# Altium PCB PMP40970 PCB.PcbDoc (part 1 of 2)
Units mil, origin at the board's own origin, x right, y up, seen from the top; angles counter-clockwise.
Board outline 1445 x 1417.32 mil, 2 copper layers (Top Layer, Bottom Layer), stack 64.8 mil thick; 72 components, 33 nets, 177 pads, 86 vias.
Unrouted connection lines stored in the file: 44.
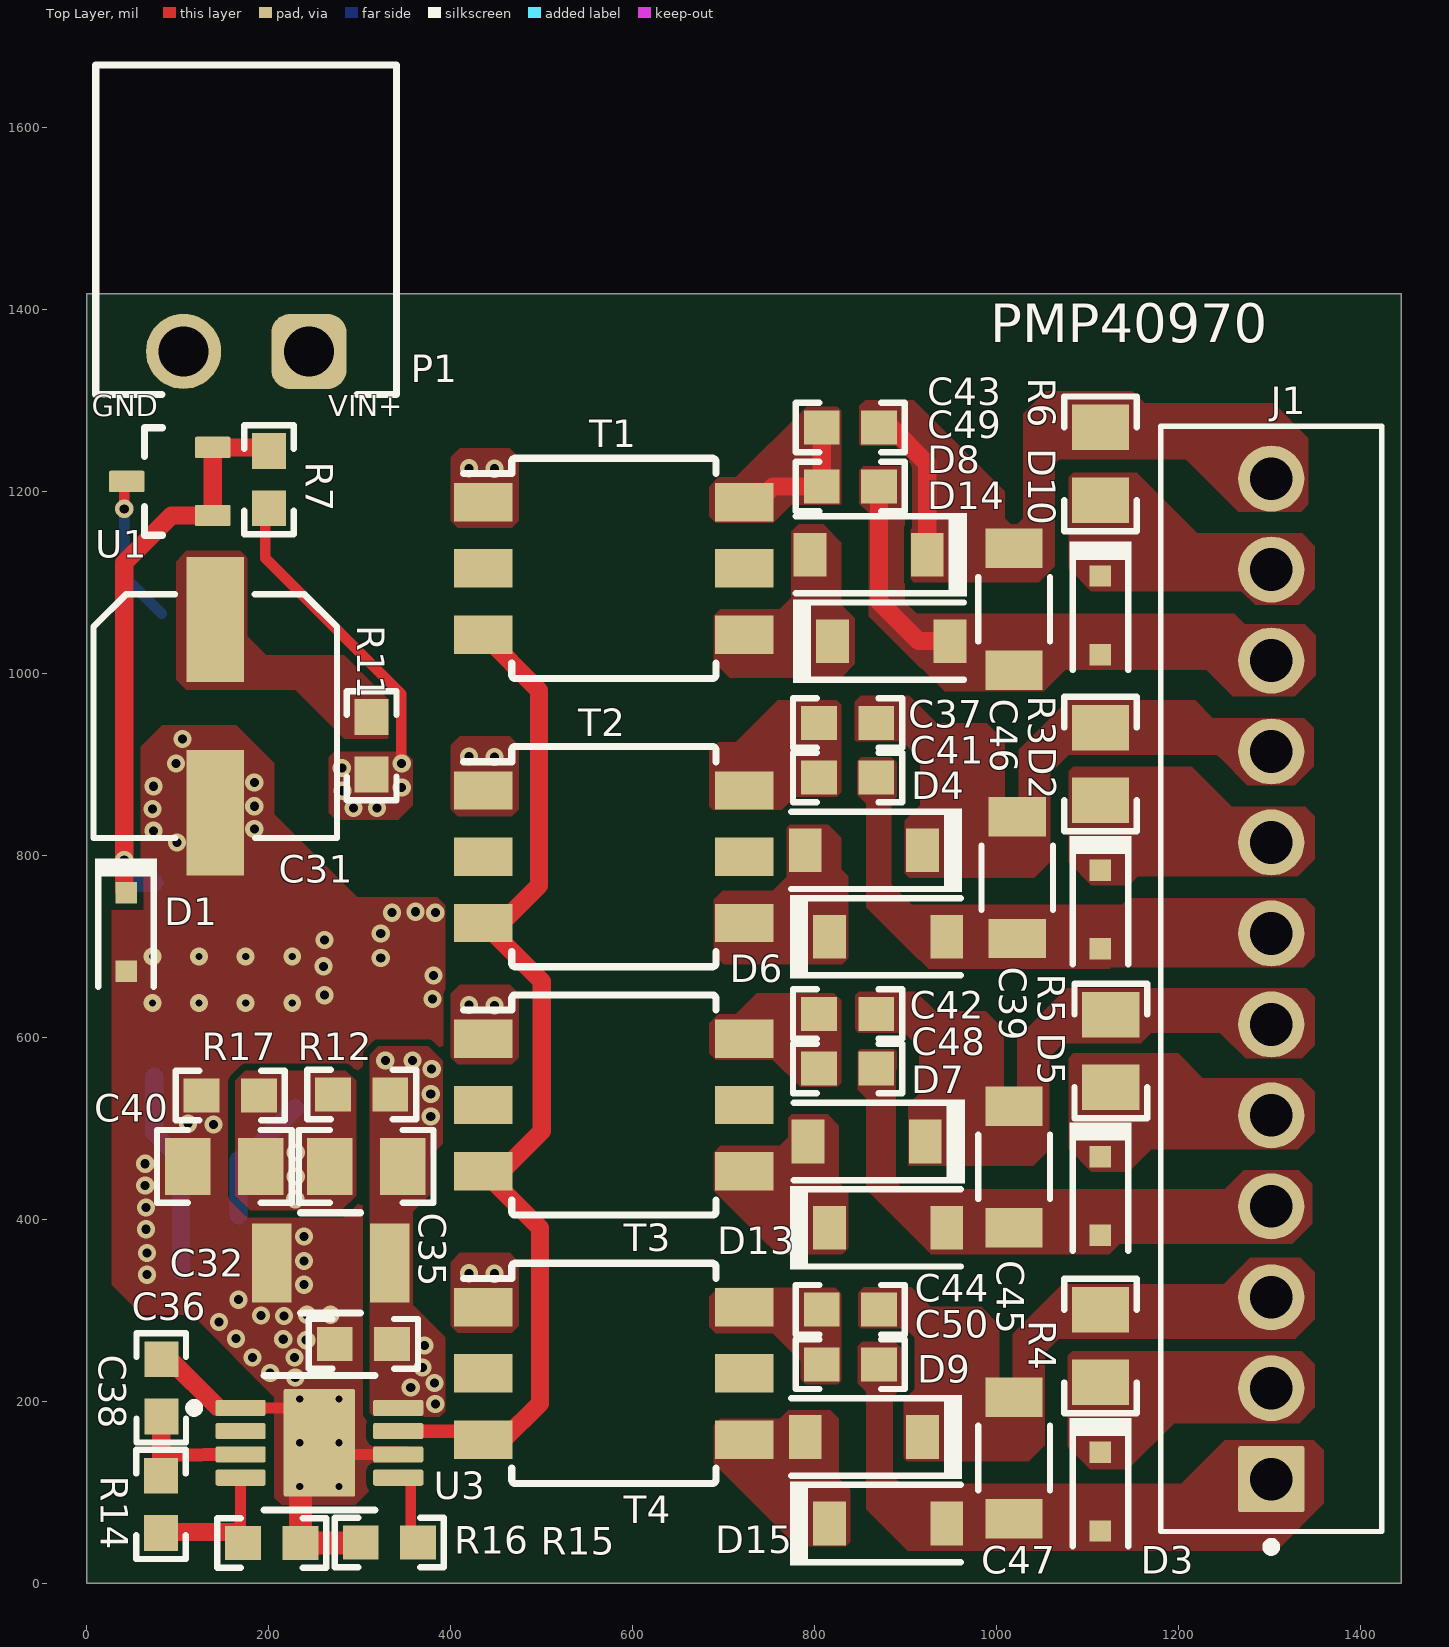
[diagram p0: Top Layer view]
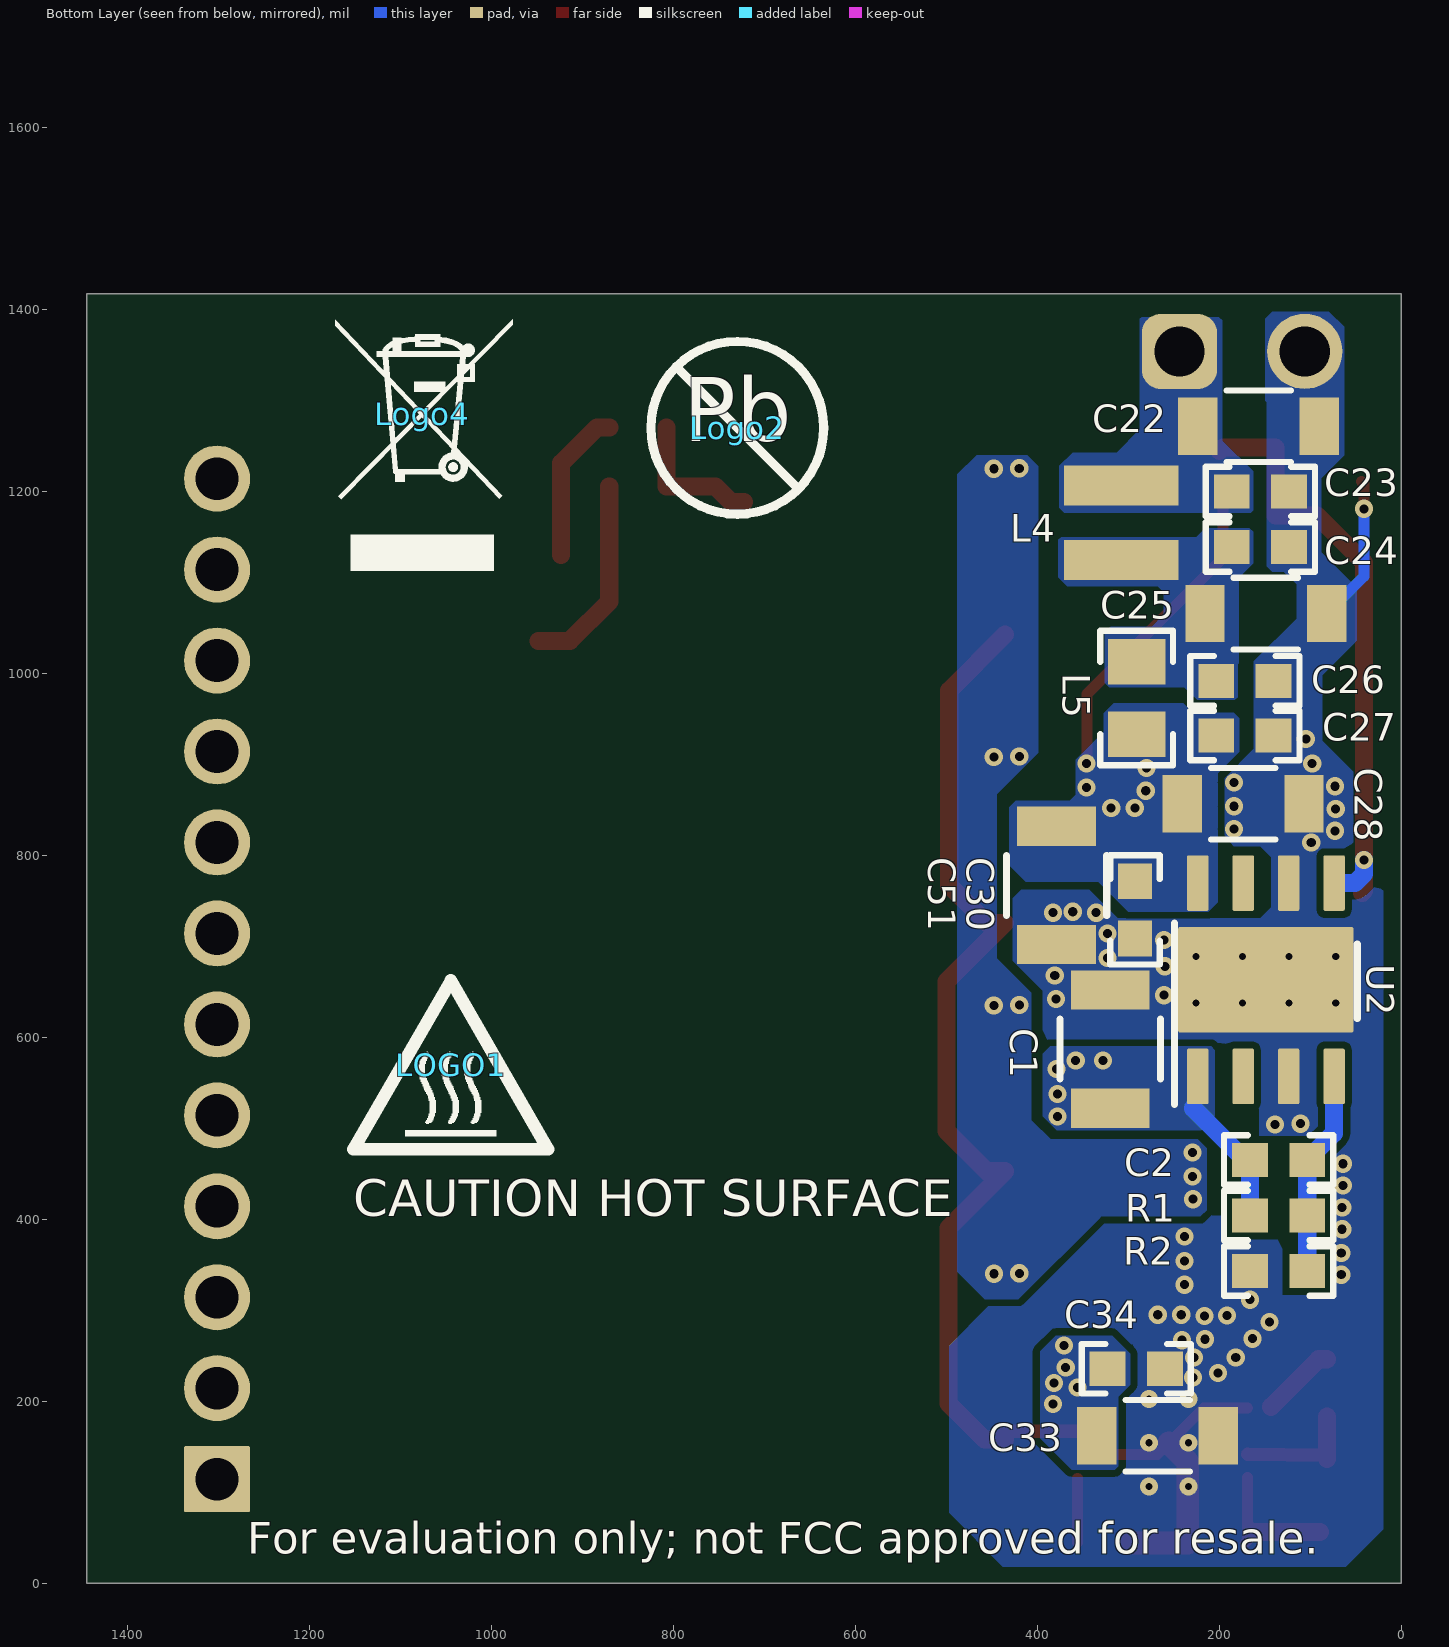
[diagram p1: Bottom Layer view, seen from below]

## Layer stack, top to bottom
Top Solder: solder mask 0.4, Solder Resist, Dk 3.5
Top Layer: signal copper 2.8
Dielectric1: core 59.2, FR-4 High Tg, Dk 4.8
Bottom Layer: signal copper 2.8
Bottom Solder: solder mask 0.4, Solder Resist, Dk 3.5

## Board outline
0,0 1445,0 1445,1417.32 0,1417.32

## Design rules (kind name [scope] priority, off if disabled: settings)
AcuteAngle [All] p1: minimum=4.50000000000000E+0001 checktracksonly=FALSE
AssemblyTestPointUsage [All] p1: valid=2
Clearance Clearance_BoardEdge_MountingHoles [OnCopper and InComponentClass('Mounting Holes') vs IsKeepOut] p1: gap=40 ignorepadtopadclearanceinfootprint=FALSE except(0: Arc-Hole Track-Hole SMDPad-Hole THPad-Hole Via-Hole Fill-Hole Poly-Hole Region-Hole Text-Hole)
Clearance Clearance_BoardEdge_Poly [OnCopper and InPoly vs IsKeepOut] p2: gap=25 ignorepadtopadclearanceinfootprint=FALSE except(0: Arc-Hole Track-Hole SMDPad-Hole THPad-Hole Via-Hole Fill-Hole Poly-Hole Region-Hole Text-Hole)
Clearance Clearance_BoardEdge [OnCopper and Not InComponentClass('Logo') and not InComponentClass('FiducialMark') and not InRegion(1000,500,4000,800) and Not IsKeepout vs IsKeepOut] p3: gap=5 ignorepadtopadclearanceinfootprint=FALSE except(0: Arc-Hole Track-Hole SMDPad-Hole THPad-Hole Via-Hole Fill-Hole Poly-Hole Region-Hole Text-Hole)
Clearance Clearance_Poly [InPolygon] p4: gap=7.8 ignorepadtopadclearanceinfootprint=FALSE
Clearance [All] p5: gap=7.8 ignorepadtopadclearanceinfootprint=FALSE
ComponentClearance ComponentClearance_Logo [All] p1: gap=10 collisioncheckmode=3 verticalgap=10 showdistances=TRUE
ComponentClearance ComponentClearance_ScrewToNut [(HasFootprint('NY PMS 440 0025 PH')) vs (HasFootprint('Keystone_1902C'))] p2: gap=5 collisioncheckmode=3 verticalgap=10 showdistances=FALSE
ComponentClearance ComponentClearance_MountingHoles [InComponentClass('Mounting Holes')] p3: gap=10 collisioncheckmode=3 verticalgap=100000 showdistances=FALSE
ComponentClearance ComponentClearance_SmallPassives [HasFootprint('0201*') or HasFootprint('0402*') or HasFootprint('0508') or HasFootprint('0603*') or HasFootprint('0612') or HasFootprint('0805*') or HasFootprint('0815*') or HasFootprint('0830*') or HasFootprint('1206*') or HasFootprint('1210*') or HasFootprint('1808*') or HasFootprint('1812*') or HasFootprint('1825*') or HasFootprint('2010*') or HasFootprint('2220*') or HasFootprint('2225*') or HasFootprint('2512*') or HasFootprint('2728*') or HasFootprint('3518*') vs HasFootprint('0201*') or HasFootprint('0402*') or HasFootprint('0508') or HasFootprint('0603*') or HasFootprint('0612') or HasFootprint('0805*') or HasFootprint('0815*') or HasFootprint('0830*') or HasFootprint('1206*') or HasFootprint('1210*') or HasFootprint('1808*') or HasFootprint('1812*') or HasFootprint('1825*') or HasFootprint('2010*') or HasFootprint('2220*') or HasFootprint('2225*') or HasFootprint('2512*') or HasFootprint('2728*') or HasFootprint('3518*')] p4: gap=10 collisioncheckmode=3 verticalgap=10 showdistances=FALSE
ComponentClearance ComponentClearance_THtoSMT [IsThruComponent vs IsSMTComponent] p5: gap=10 collisioncheckmode=3 verticalgap=100000 showdistances=FALSE
ComponentClearance ComponentClearance_THtoTH [IsThruComponent vs IsThruComponent] p6: gap=10 collisioncheckmode=3 verticalgap=100000 showdistances=FALSE
ComponentClearance [All] p7: gap=10 collisioncheckmode=3 verticalgap=10 showdistances=FALSE
DiffPairsRouting [All] p1: maxlimit=100 minlimit=10 mostfreqgap=10 toplayer_minwidth=15 toplayer_maxwidth=15 toplayer_prefwidth=15 bottomlayer_minwidth=15 bottomlayer_maxwidth=15 bottomlayer_prefwidth=15 maxuncoupledlength=1000
FabricationTestPointUsage TestPointUsage [All] p1: valid=2 allowmultiple=FALSE
FabricationTestpoint Testpoint [All] p1: side=3 testpointundercomponent=TRUE minsize=40 maxsize=100 preferedsize=60 minholesize=0 maxholesize=40 preferedholesize=32 testpointgrid=1 allowsidetop=TRUE allowsidebottom=TRUE usegrid=TRUE gridtolerance=0.01
FanoutControl Fanout_LCC [IsLCC] p1: bgadir=Out bgaviamode=Centered fanoutstyle=Auto fanoutdirection=Alternating viagrid=1 // Fanout_LCC (Default Rule)
FanoutControl Fanout_BGA [IsBGA] p2: bgadir=Out bgaviamode=Centered fanoutstyle=Auto fanoutdirection=Alternating viagrid=1 // Fanout_BGA (Default Rule)
FanoutControl Fanout_Default [All] p4: bgadir=Out bgaviamode=Centered fanoutstyle=Auto fanoutdirection=Alternating viagrid=1 // Fanout_Default (Default Rule)
FanoutControl Fanout_Small [(CompPinCount < 5)] p5: bgadir=Out bgaviamode=Centered fanoutstyle=Auto fanoutdirection=OutThenIn viagrid=1 // Fanout_Small (Default Rule)
HoleSize [All] p1: absolutevalues=TRUE maxlimit=251 minlimit=6 maxpercent=80.000 minpercent=20.000
MinimumAnnularRing [All] p1: minimumring=3
MinimumSolderMaskSliver MinimumSolderMaskSliver_Logo [InComponentClass('Logo') vs InComponentClass('Logo')] p1: minsoldermaskwidth=0.7
MinimumSolderMaskSliver [All] p2: minsoldermaskwidth=0
PlaneConnect [All] p1: planeconnectstyle=Direct reliefexpansion=10 reliefentries=4 reliefconductorwidth=10 reliefairgap=10
PolygonConnect [All] p1: connectstyle=Direct reliefconductorwidth=10 reliefentries=4 polygonreliefangle="90 Angle" airgapwidth=10
RoutingCorners [All] p1: cornerstyle=45-Degree minsetback=10 maxsetback=100
RoutingVias [All] p1: holewidth=16 width=34 viastyle="Through Hole" minholewidth=8 minwidth=16 maxholewidth=40 maxwidth=65
SMDToCorner [All] p1: distance=0
SilkToBoardRegionClearance [Not ((IsComment or IsDesignator) And (Hide <> 'False')) and not InRegion(1000,500,4000,800)] p1:
SilkToSilkClearance [All] p1: silktosilkclearance=0
SilkToSolderMaskClearance SilkscreenOverComponentPads [IsPad] p1: minsilkscreentomaskgap=0 clearancetoexposedcopper=TRUE
SolderMaskExpansion [All] p1: expansion=3
Width [All] p1: maxlimit=100 minlimit=6 preferedwidth=10 checkconnectedcopper=TRUE
14 further rules are at their usual default settings.

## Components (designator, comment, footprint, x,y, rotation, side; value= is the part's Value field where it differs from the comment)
C1 "UMK325AB7106KMHT" 1210_280 319.98,587 r90 bottom value=10uF
C2 "CGA3E2X7R1H473K080AA" 0603 135,404 r180 bottom value=0.047uF
C22 "GCM31CR71H225KA55L" 1206_180 156.95,1271.65 r180 bottom value=2.2uF
C23 "C0603C222K5RACTU" 0603 154.88,1199.84 r180 bottom value=2200pF
C24 "C0603C222K5RACTU" 0603 154.88,1138.84 r180 bottom value=2200pF
C25 "GCM31CR71H225KA55L" 1206_180 148.88,1065.84 r180 bottom value=2.2uF
C26 "C0603C222K5RACTU" 0603 171.88,991.84 r180 bottom value=2200pF
C27 "C0603C222K5RACTU" 0603 171.88,931.84 r180 bottom value=2200pF
C28 "GCM31CR71H225KA55L" 1206_180 173.88,856.81 r180 bottom value=2.2uF
C30 "06035C104KAZ2A" 0603 293,740 r270 bottom value=0.1uF
C31 "EEHZC1H330XP" SM_RADIAL_6.3BMM 141,953.01 r270 top value=33uF
C32 "UMK325AB7106KMHT" 1210_280 268,352 r180 top value=10uF
C33 "CGA5L3X7R1H475K160AE" 1206_190 268,162 r0 bottom value=4.7uF
C34 "06035C104KAZ2A" 0603 291.45,235.6 r180 bottom value=0.1uF
C35 "CGA4J3X7R1H105K125AB" 0805_HV 307,458 r180 top value=1uF
C36 "06035C104KAZ2A" 0603 304,263.02 r180 top value=0.1uF
C37 "C0603C223K5RACTU" 0603 836.21,945.51 r180 top value=0.022uF
C38 "CGA3E1X7R1E105K080AC" 0603 81.74,214.49 r90 top value=1uF
C39 "CGA5L1X7R1H106K160AC" 1206_190 1022.62,775.51 r270 top value=10uF
C40 "CGA4J3X7R1H105K125AB" 0805_HV 151,458 r180 top value=1uF
C41 "C0603C223K5RACTU" 0603 836.21,885.51 r0 top value=0.022uF
C42 "C0603C223K5RACTU" 0603 836.21,625.51 r180 top value=0.022uF
C43 "C0603C223K5RACTU" 0603 839.24,1270.51 r180 top value=0.022uF
C44 "C0603C223K5RACTU" 0603 839.24,300.51 r180 top value=0.022uF
C45 "CGA5L1X7R1H106K160AC" 1206_190 1019.24,457.44 r270 top value=10uF
C46 "CGA5L1X7R1H106K160AC" 1206_190 1019.24,1070.51 r270 top value=10uF
C47 "CGA5L1X7R1H106K160AC" 1206_190 1019.24,137.44 r270 top value=10uF
C48 "C0603C223K5RACTU" 0603 836.21,565.51 r0 top value=0.022uF
C49 "C0603C223K5RACTU" 0603 839.24,1205.51 r0 top value=0.022uF
C50 "C0603C223K5RACTU" 0603 839.24,240.51 r0 top value=0.022uF
C51 "UMK325AB7106KMHT" 1210_280 379,767 r270 bottom value=10uF
D1 "MMSZ5226BS-7-F" SOD-323 43,715.69 r270 top value=3.3V
D2 "BZT52C5V1S-7-F" SOD-323 1114.24,740.51 r270 top value=5.1V
D3 "BZT52C5V1S-7-F" SOD-323 1114.24,100.51 r270 top value=5.1V
D4 "PMEG6010CEGWJ" SOD-123 854.24,805.51 r180 top value=60V
D5 "BZT52C5V1S-7-F" SOD-323 1114.24,425.51 r270 top value=5.1V
D6 "PMEG6010CEGWJ" SOD-123 880.73,710.51 r0 top value=60V
D7 "PMEG6010CEGWJ" SOD-123 857.18,485.51 r180 top value=60V
D8 "PMEG6010CEGWJ" SOD-123 859.24,1130.51 r180 top value=60V
D9 "PMEG6010CEGWJ" SOD-123 854.24,160.51 r180 top value=60V
D10 "BZT52C5V1S-7-F" SOD-323 1114.24,1063.82 r270 top value=5.1V
D13 "PMEG6010CEGWJ" SOD-123 880.73,390.51 r0 top value=60V
D14 "PMEG6010CEGWJ" SOD-123 884.24,1035.51 r0 top value=60V
D15 "PMEG6010CEGWJ" SOD-123 880.73,65.51 r0 top value=60V
J1 "LHA-12-TS" FP-LHA-12-TS_HDR12-MFG 1302,664.17 r90 top
L4 "XFL3010-102MEB" XFL3010 307.88,1165.84 r270 bottom value=1uH
L5 "782853152" 0805_HV 291,973 r270 bottom value="1500 ohm"
LOGO1 "CAUTION HOT SURFACE" IEC_HotSurface_Small 1045,570 r180 bottom
Logo2 "Pb-Free Symbol" Pb-Free_Overlay_Medium 730,1270 r180 bottom
Logo3 "FCC disclaimer" FCC_disclaimer 1773,621 r90 top
Logo4 "WEEE logo" WEEE_Minimum 1076.5,1285.17 r180 bottom
P1 "691322110002" 691322110002 175.1,1487.86 r180 top
R1 "CRCW060310K0FKEA" 0603 135,465 r0 bottom value=10.0k
R2 "CRCW060310K0FKEA" 0603 135,343 r0 bottom value=10.0k
R3 "CRCW08055K10JNEA" 0805_HV 1114.24,900.51 r90 top value=5.1k
R4 "CRCW08055K10JNEA" 0805_HV 1114.24,260.51 r90 top value=5.1k
R5 "CRCW08055K10JNEA" 0805_HV 1125.67,585 r90 top value=5.1k
R6 "CRCW08055K10JNEA" 0805_HV 1114.24,1230.51 r90 top value=5.1k
R7 "RC0603FR-0720KL" 0603 200,1213.01 r270 top value=20.0k
R11 "CRCW06031R00FKEA" 0603 313,920.5 r270 top value=1.00
R12 "CRCW060310K0FKEA" 0603 302,537 r0 top value=10.0k
R14 "RC0603FR-0716KL" 0603 81.54,86.48 r90 top value=16.0k
R15 "RC0603FR-07100KL" 0603 332.44,44.49 r0 top value=100k
R16 "RC0603FR-0716KL" 0603 203.19,43.99 r180 top value=16.0k
R17 "CRCW060310K0FKEA" 0603 157.5,536 r0 top value=10.0k
T1 "760301107" Wurth_WE-GDT_EP5 579.24,1115.51 r0 top value=650uH
T2 "760301107" Wurth_WE-GDT_EP5 579.23,798.57 r0 top value=650uH
T3 "760301107" Wurth_WE-GDT_EP5 579.22,525.51 r0 top value=650uH
T4 "760301107" Wurth_WE-GDT_EP5 579.21,230.51 r0 top value=650uH
U1 "TL431BQDBZRQ1" DBZ0003A_N 91,1211.04 r180 top
U2 "TPS7B4254QDDARQ1" DDA0008J 148.92,663.25 r90 bottom
U3 "UCC25800DGNRQ1" DGN0008G-MFG 255.58,154.2 r0 top

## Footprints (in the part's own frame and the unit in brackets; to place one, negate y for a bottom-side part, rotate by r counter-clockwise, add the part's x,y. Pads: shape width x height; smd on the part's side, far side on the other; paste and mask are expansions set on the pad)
0603 [mm] "0603 from SM-752 data"
  rect 1x0.95 smd: 1(-0.8,0) 2(0.8,0)
  silkscreen extent -1.52,-0.69 1.52,0.69, body extent -0.87,-0.47 0.87,0.47, height 1
0805_HV [mil] "0805 with 30mil clearance between pads"
  rect 50x63 smd: 1(-40,0) 2(40,0)
  silkscreen extent -74,-40 74,40, body extent -43,-29 43,29, height 57
1206_180 [mm] "1206_180"
  rect 1.1x1.6 smd: 1(-1.7,0) 2(1.7,0)
  silkscreen extent -0.9,-1 0.9,1, body extent -1.75,-0.95 1.75,0.95, height 1.8
1206_190 [mm] "1206_190"
  rect 1.1x1.6 smd: 1(-1.7,0) 2(1.7,0)
  silkscreen extent -0.9,-1 0.9,1, body extent -1.75,-0.95 1.75,0.95, height 1.9
1210_280 [mm] "SMD, 2-Leads, Body 3.6x2.8mm, Height 2.8mm"
  rect 1.1x2.2 smd: 1(-1.65,0) 2(1.65,0)
  silkscreen extent -0.84,-1.4 0.84,1.4, body extent -1.8,-1.4 1.8,1.4, height 2.8
691322110002 [mm] "Horizontal PCB Header, pitch 3.5mm, 02p"
  rrect50% 2.1x2.1 hole 1.4: 1(-1.75,3.4)
  round 2.1 hole 1.4: 2(1.75,3.4)
  silkscreen extent -4.2,-4.6 4.2,4.6, body extent -4.2,-4.6 4.2,4.6, height 7.3
DBZ0003A_N [mm] "SOT23, 3-Leads, Body 2.9x1.3mm, Pitch 0.95mm, Lead Span 2.4mm, IPC Medium Density"
  rrect17% 1x0.6 smd: 1(-1.2,0.95) 2(-1.2,-0.95) 3(1.2,0)
  silkscreen extent 0.2,-1.5 0.7,1.5, body extent -1.26,-1.46 1.26,1.46, height 0.98
DDA0008J [mm] "SOIC, 8-Leads, Body 4.9x3.9mm, Pitch 1.27mm, Exposed Pad"
  rrect14% 1.55x0.6 smd: 1(-2.7,1.905) 2(-2.7,0.635) 3(-2.7,-0.635) 4(-2.7,-1.905) 5(2.7,-1.905) 6(2.7,-0.635) 7(2.7,0.635) 8(2.7,1.905)
  rrect4% 2.95x4.9 smd paste-1.5 mask-1.5: 9(0,0)
  silkscreen extent -3.47,-2.55 1.58,2.55, body extent -3.01,-2.45 3.01,2.45, height 1.57
DGN0008G-MFG [mm]
  rrect22% 1.4x0.45 smd paste+0 mask+0: 1(-2.2,0.975) 2(-2.2,0.325) 3(-2.2,-0.325) 4(-2.2,-0.975) 5(2.2,-0.975) 6(2.2,-0.325) 7(2.2,0.325) 8(2.2,0.975)
  rrect5% 2x3 smd paste-1000 mask-1000: 9(0,0)
  silkscreen extent -3.62,-1.88 1.55,1.88, body extent -3,-1.8 3,1.8, height 0.25
FCC_disclaimer [mil]
FP-LHA-12-TS_HDR12-MFG [mil]
  rrect5% 72.59x72.59 hole 47 paste-39370.1 mask+0: 1(-550,0)
  round 72.59 hole 47 paste-39370.1 mask+0: 2(-450,0) 3(-350,0) 4(-250,0) 5(-150,0) 6(-50,0) 7(50,0) 8(150,0) 9(250,0) 10(350,0) 11(450,0) 12(550,0)
  silkscreen extent -629,-122 608,122, body extent -611,-125 611,125, height 10
IEC_HotSurface_Small [mil]
  silkscreen extent -107,-93 107,92
Pb-Free_Overlay_Medium [mil]
  silkscreen extent -95,-95 95,95
SM_RADIAL_6.3BMM [mm] "Nichicon 6.3x7.7"
  rect 3.5x1.6 smd: 1(-2.7,0) 2(2.7,0)
  silkscreen extent -3.4,-3.4 3.4,3.4, body extent -3.4,-3.4 3.4,3.4, height 8
SOD-123 [mm] "On Semi recommended land pattern"
  rect 0.915x1.22 smd: 1(-1.637,0) 2(1.637,0)
  silkscreen extent -2.74,-1.17 2.03,1.17, body extent -1.93,-0.9 1.93,0.9, height 1.35
SOD-323 [mm] "NXP recommended land pattern"
  rect 0.6x0.6 smd paste-0.05: 1(-1.1,0) 2(1.1,0)
  silkscreen extent -2.06,-0.86 1.53,0.86, body extent -1.3,-0.67 1.3,0.68, height 1.1
WEEE_Minimum [mil] "WEEElie bin"
  silkscreen extent -95,-172 99,104
Wurth_WE-GDT_EP5 [mm] "Gate Drive Transformer, EP5"
  rect 1.63x1.07 smd: 1(-3.645,1.85) 2(-3.645,0) 3(-3.645,-1.85) 4(3.645,-1.85) 5(3.645,0) 6(3.645,1.85)
  silkscreen extent -4.2,-3.08 2.85,3.08, body extent -3.85,-3.08 3.85,3.07, height 5.12
XFL3010 [mm] "Coilcraft"
  rect 1.12x3.2 smd: 1(-1.04,0) 2(1.04,0)
  body extent -1.6,-1.6 1.6,1.6, height 1.1

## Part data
C1 C32 C51: library part CMP-0009258-2, "CAP, CERM, 10 uF, 50 V, +/- 10%, X7R, AEC-Q200 Grade 1, 1210", Cap_Case=1210, MANUFACTURER="Taiyo Yuden", Supplier Part Number 1=587-4326-1-ND, TempCo=X7R, Tolerance_%=10%, Value1=Unknown, Value2=50V, ValueDisplayed=10uF
C2: library part CMP-0007079-2, "CAP, CERM, 0.047 uF, 50 V, +/- 10%, X7R, AEC-Q200 Grade 1, 0603", Cap_Case=0603, MANUFACTURER=TDK, Supplier Part Number 1=445-5664-1-ND, TempCo=X7R, Tolerance_%=10%, Value1="0.049007 ohm", Value2=50V, ValueDisplayed=0.047uF
C22 C25 C28: library part CMP-0008814-2, "CAP, CERM, 2.2 uF, 50 V, +/- 10%, X7R, AEC-Q200 Grade 1, 1206", Cap_Case=1206, MANUFACTURER=MuRata, Supplier Part Number 1=490-4796-1-ND, TempCo=X7R, Tolerance_%=10%, Value1=Unknown, Value2=50V, ValueDisplayed=2.2uF
C23 C24 C26 C27: library part CMP-0006898-4, "CAP, CERM, 2200 pF, 50 V, +/- 10%, X7R, 0603", Cap_Case=0603, MANUFACTURER=Kemet, Supplier Part Number 1=399-1085-1-ND, TempCo=X7R, Tolerance_%=10%, Value1=Unknown, Value2=50V, ValueDisplayed=2200pF
C30 C34 C36: library part CMP-0079095-1, "CAP, CERM, 0.1 µF, 50 V,+/- 10%, X7R, AEC-Q200 Grade 1, 0603", Cap_Case=0603, MANUFACTURER=AVX, Supplier Part Number 1=478-3540-1-ND, TempCo=X7R, Tolerance_%=10%, Value2=50V, ValueDisplayed=0.1µF
C31: library part CMP-0012598-3, "CAP, Polymer Hybrid, 33 uF, 50 V, +/- 20%, 40 ohm, 6.3x7.7 SMD", MANUFACTURER=Panasonic, Supplier Part Number 1=P15464CT-ND, Tolerance_%=20%, Value1="40 ohm", Value2=50V, ValueDisplayed=33uF
C33: library part CMP-0085349-1, "CAP, CERM, 4.7 µF, 50 V,+/- 10%, X7R, AEC-Q200 Grade 1, 1206", Cap_Case=1206, MANUFACTURER=TDK, TempCo=X7R, Tolerance_%=10%, Value2=50V, ValueDisplayed=4.7µF
C35 C40: library part CMP-0007976-2, "CAP, CERM, 1 uF, 50 V, +/- 10%, X7R, AEC-Q200 Grade 1, 0805", Cap_Case=0805, MANUFACTURER=TDK, Supplier Part Number 1=445-6961-1-ND, TempCo=X7R, Tolerance_%=10%, Value1="0.008782 ohm", Value2=50V, ValueDisplayed=1uF
C37 C41 C42 C43 C44 C48 C49 C50: library part CMP-0006901-1, "CAP, CERM, 0.022 uF, 50 V, +/- 10%, X7R, 0603", Cap_Case=0603, MANUFACTURER=Kemet, Supplier Part Number 1=399-1280-1-ND, TempCo=X7R, Tolerance_%=10%, Value1=Unknown, Value2=50V, ValueDisplayed=0.022uF
C38: library part CMP-0076705-3, "CAP, CERM, 1 µF, 25 V,+/- 10%, X7R, AEC-Q200 Grade 1, 0603", Cap_Case=1.6x0.8x0.8mm, MANUFACTURER=TDK, Supplier Part Number 1=445-6931-1-ND, TempCo=X7R, Tolerance_%=10%, Value2=25V, ValueDisplayed=1µF
C39 C45 C46 C47: library part CMP-0085950-1, "CAP, CERM, 10 µF, 50 V,+/- 10%, X7R, AEC-Q200 Grade 1, 1206", Cap_Case=1206, MANUFACTURER=TDK, TempCo=X7R, Tolerance_%=10%, Value2=50V, ValueDisplayed=10µF
D1: library part CMP-0005849-3, "Diode, Zener, 3.3 V, 200 mW, SOD-323", MANUFACTURER="Diodes Inc.", Power_W=200mW, Value1=0.2W
D2 D3 D5 D10: library part CMP-0005865-2, "Diode, Zener, 5.1 V, 200 mW, SOD-323", MANUFACTURER="Diodes Inc.", Power_W=200mW, Value1=0.2W
D4 D6 D7 D8 D9 D13 D14 D15: library part CMP-0079239-1, "Diode, Schottky, 60 V, 1 A, AEC-Q101, SOD-123", MANUFACTURER=Nexperia, Supplier Part Number 1=1727-7340-1-ND, Value1=1A, Value2=0.66V
J1: library part CMP-0089369-1, Current_A=3A, Digikey Part Number=2057-LHA-12-TS-ND, MANUFACTURER="Adam Tech", Operating Temperature Range="-25°C to +85°C", Voltage_V=250V
L4: library part CMP-0061128-1, "Inductor, Shielded, Composite, 1 uH, 2.3 A, 0.04 ohm, SMD", MANUFACTURER=Coilcraft, Value1="0.04 ohm", Value2=2.3A, ValueDisplayed=1uH
L5: library part CMP-0003295-1, "Ferrite Bead, 1500 ohm @ 100 MHz, 0.7 A, 0805", MANUFACTURER="Wurth Elektronik", Supplier Part Number 1=732-6714-1-ND, Value1="0.3 ohm", Value2=0.7A, ValueDisplayed="1500 ohm"
LOGO1: library part CMP-0074837-1, "IEC 61010-1 Hot Surface Warning"
Logo2: library part CMP-0074839-1
Logo3: library part CMP-0074847-1, "FCC_disclaimer"
Logo4: library part CMP-0074769-1
P1: "WR-TBL Serie 3221 Horizontal PCB Header, Pluggable, THT, pitch 3.5mm, 2p", MANUFACTURER="Wurth Elektronik", Operating Temperature="-40 to +105degC", Rated Current [UL]=10A, Working Voltage [UL]=300VAC
R1 R2 R12 R17: library part CMP-0021998-4, "RES, 10.0 k, 1%, 0.1 W, AEC-Q200 Grade 0, 0603", MANUFACTURER=Vishay-Dale, Power_W=100mW, Supplier Part Number 1=541-10.0KHCT-ND, TempCo="100 ppm/C", Tolerance_%=1%, Value2=0.1W, Value_Code=10k0, ValueDisplayed=10.0k
R3 R4 R5 R6: library part CMP-0020572-3, "RES, 5.1 k, 5%, 0.125 W, AEC-Q200 Grade 0, 0805", MANUFACTURER=Vishay-Dale, Power_W=125mW, Supplier Part Number 1=541-5.1KACT-ND, TempCo="200 ppm/C", Tolerance_%=5%, Value2=0.125W, Value_Code=5k10, ValueDisplayed=5.1k
R7: library part CMP-0022906-4, "RES, 20.0 k, 1%, 0.1 W, 0603", MANUFACTURER="Yageo America", Power_W=100mW, Supplier Part Number 1=311-20.0KHRCT-ND, TempCo="100 ppm/C", Tolerance_%=1%, Value2=0.1W, Value_Code=20k0, ValueDisplayed=20.0k
R11: library part CMP-0022170-2, "RES, 1.00, 1%, 0.1 W, 0603", MANUFACTURER=Vishay-Dale, Power_W=100mW, Supplier Part Number 1=52K8059, TempCo="100 ppm/C", Tolerance_%=1%, Value2=0.1W, Value_Code=1R00, ValueDisplayed=1.00
R14 R16: library part CMP-0022831-4, "RES, 16.0 k, 1%, 0.1 W, 0603", MANUFACTURER="Yageo America", Power_W=100mW, Supplier Part Number 1=311-16.0KHRCT-ND, TempCo="100 ppm/C", Tolerance_%=1%, Value2=0.1W, Value_Code=16k0, ValueDisplayed=16.0k
R15: library part CMP-0022735-3, "RES, 100 k, 1%, 0.1 W, 0603", MANUFACTURER="Yageo America", Power_W=100mW, Supplier Part Number 1=311-100KHRCT-ND, TempCo="200 ppm/C", Tolerance_%=1%, Value2=0.1W, Value_Code=100k
T1 T2 T3 T4: library part CMP-0030729-1, "Transformer, Gate Drive, 650 uH, SMT", MANUFACTURER="Wurth Elektronik", Supplier Part Number 1=732-4287-1-ND, ValueDisplayed=650uH
U1: library part CMP-0032986-1, "Automotive Catalog Adjustable Precision Shunt Regulator, 34 ppm / degC, 100 mA, -40 to 125 degC, 3-pin SOT-23 (DBZ), Green (RoHS & no Sb/Br)", MANUFACTURER="Texas Instruments", Rating=Automotive, Temp Coeff(Typ)(ppm/ degree C)=34
U2: library part CMP-0073874-1, "150-mA 40-V Voltage-Tracking LDO With 4-mV Tracking Tolerance, DDA0008J (SOIC-8)", Alternate Manufacturer="Texas Instruments"
U3: library part CMP-0088494-2, "Open Loop LLC Transformer Driver for Isolated Bias Supplies", MANUFACTURER="Texas Instruments", Max Supply Voltage=36V, Min Supply Voltage=12V, Nominal Supply Current=500uA, Operating Temperature Range="-40°C to +150°C", Switching Frequency=100-2000kHz

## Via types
v1: diameter 20, hole 10, Top Layer to Bottom Layer, 72 vias
v2: diameter 19.68, hole 7.87, Top Layer to Bottom Layer, 10 vias
v3: diameter 19.68, hole 7.87, Top Layer to Bottom Layer, tented both sides, 4 vias

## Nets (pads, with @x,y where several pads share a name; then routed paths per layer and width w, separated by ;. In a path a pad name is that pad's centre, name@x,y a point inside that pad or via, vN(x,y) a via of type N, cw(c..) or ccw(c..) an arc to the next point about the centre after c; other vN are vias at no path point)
18V_1: C43.1 C46.1 D8.1 J1.12 R6.2 | length 169.9
  Top Layer w20: C43.1@870.73,1270.51 884.24,1270.51 923.71,1231.04 D8.1@923.71,1130.51
18V_2: C37.1 C39.1 D4.1 J1.9 R3.2
18V_3: C42.1 C45.1 D7.1 J1.6 R5.2
18V_4: C44.1 C47.1 D9.1 J1.3 R4.2
20V: C1.1 C2.1 C32.1 C33.2 C34.1 C35.1 C36.1 R1.2 R12.2 U2.1 U3.8 | length 147.1
  Bottom Layer w20: C2.1@166.5,404 R1.2@166.5,465 171.96,465 229,522.04
  other v1: 383,197 356,215 382,220 369,237 371,261 378,513 378,537.66 379,565 328,574.62 358,574.62
-5V_1: C46.2 C49.2 D10.2 D14.2 J1.10 | length 222.5
  Top Layer w20: C49.2@870.73,1205.51 870.73,1079.01 914.24,1035.51 D14.2@948.71,1035.51
-5V_2: C39.2 C41.2 D2.2 D6.2 J1.7
-5V_3: C45.2 C48.2 D5.2 D13.2 J1.4
-5V_4: C47.2 C50.2 D3.2 D15.2 J1.1
GND: C1.2 C22.2 C23.2 C24.2 C25.2 C26.2 C27.2 C28.2 C30.2 C31.2 C32.2 C33.1 C34.2 C36.2 C38.2 C40.2 C51.2 D1.2 P1.2 R2.2 R15.1 R16.1 R17.1 U1.3 U2.3 U2.6 U2.9 U3.1 U3.6 U3.9 | length 626.2
  Top Layer w12: v1(41,1181) 41,1208.29 U1.3@43.76,1211.04 ; U3.1@168.96,192.59 217.19,192.59 U3.9@255.58,154.2 268.37,141.41 U3.6@342.19,141.41
  Top Layer w20: C38.2@81.74,245.98 91.02,245.98 U3.1@143.27,193.73
  Top Layer w25: U3.9@255.58,154.2 234.68,133.31 R16.1@234.68,43.99 300.44,43.99 R15.1@300.94,44.49
  Bottom Layer w12: v1(41,1181) 41,1106.79 C25.2@81.95,1065.84
  other v1: 229,226 201.43,231 182,248 228,248 241,267 215.8,268 163.77,268.66 145,287 191.49,294 216.5,293.66 242,295 267.75,295 166.5,311.5 238.5,328 66,339 238.5,354 66,362.84 238.5,381 65,389 65,413 64,437 64,461 139,504 111,505 379.8,642 261,646.29 381,668.01 260,678 323,687 261,707 323,714 335.5,737 383,737.01 361.23,738 99,814 73,827 184,829 72.15,851 184,854 73,876 184,880.24 98,901 105,928
  other v2: 233.92,106.17 277.23,106.17 233.92,154.2 277.23,154.2 233.92,202.23 277.23,202.23 123.33,637.66 174.51,637.66 123.33,688.84 174.51,688.84
  other v3: 72.15,637.66 225.69,637.66 72.15,688.84 225.69,688.84
HB: C35.2 C40.1 R12.1 R17.2 T1.1 T2.1 T3.1 T4.1
  other v1: 447.97,340 419.97,340.51 229,422 229.5,447 229.5,473.31 447.98,635 419.98,635.51 447.99,908.06 419.99,908.57 448,1225 420,1225.51
NetC2_2: C2.2 R1.1 R2.1 U2.4 | length 226.2
  Bottom Layer w20: U2.4@73.92,556.95 73.92,494.58 R1.1@103.5,465 R2.1@103.5,343
NetC24_1: C24.1 C25.1 C26.1 L4.2 L5.1
NetC27_1: C27.1 C28.1 C30.1 C51.1 L5.2 R7.2 R11.2 U2.8 | length 343.6
  Top Layer w12: R7.2@196,1182.5 196,1126.9 345.5,977.4 345.5,901.5 v1(346,901)
  other v1: 293,852 319,852 281,871 346,874.5 280.17,896.09
NetC31_1: C31.1 R11.1
NetC37_2: C37.2 C41.1 T2.6
NetC42_2: C42.2 C48.1 T3.6
NetC43_2: C43.2 C49.1 T1.6 | length 157.1
  Top Layer w20: T1.6@722.74,1188.35 737.07,1188.35 754.24,1205.51 C49.1@807.74,1205.51 C43.2@807.74,1270.51
NetC44_2: C44.2 C50.1 T4.6
NetD1_1: D1.1 R7.1 U1.1 U1.2 U2.5 | length 673
  Top Layer w20: D1.1@43,759 41,761 v1(41,795) 41,1121.72 92.92,1173.64 U1.1@138.24,1173.64 U1.2@138.24,1248.44 196.06,1248.44 R7.1@200,1244.51
  Bottom Layer w20: v1(41,795) 41,779.55 51,769.55 U2.5@73.92,769.55
NetD4_2: D4.2 D6.1 T2.4
NetD7_2: D7.2 D13.1 T3.4
NetD8_2: D8.2 D14.1 T1.4
NetD9_2: D9.2 D15.1 T4.4
NetR15_2: R15.2 U3.5 | length 70.7
  Top Layer w12: R15.2@355.93,44.49 U3.5@356,115.16
OC_DT: R14.1 R16.2 U3.4 | length 156.2
  Top Layer w12: R16.2@159.7,55.98 168.96,65.24 ; U3.4@168.96,115.81 168.96,65.24 ; R16.2@171.69,43.99 168.96,46.71 168.96,65.24
  Top Layer w20: R14.1@89.54,55.98 R16.2@159.7,55.98
SGND_1: D10.1 J1.11 R6.1
SGND_2: D2.1 J1.8 R3.1
SGND_3: D5.1 J1.5 R5.1
SGND_4: D3.1 J1.2 R4.1
SW: T1.3 T2.3 T3.3 T4.3 U3.7 | length 1180
  Top Layer w12: T4.3@435.71,157.68 T4.3@435.71,167
  Top Layer w15: U3.7@342.19,167 T4.3@435.71,167
  Top Layer w20: T4.3@435.71,157.68 458.17,157.68 498,197.51 498,390.39 T3.3@435.71,452.68 455.68,452.68 500,497 500,661.46 T2.3@435.73,725.73 455.73,725.73 497,767 497,981.41 T1.3@435.73,1042.68
VIN+: C22.1 C23.1 L4.1 P1.1
VREG: C38.1 R14.2 U3.3 | length 135.7
  Top Layer w12: R14.2@81.74,136.22 85.92,140.41
  Top Layer w15: 85.92,140.41 U3.3@168.96,141.41
  Top Layer w20: R14.2@81.74,136.22 C38.1@81.74,182.99
pads on no net: T1.2 T1.5 T2.2 T2.5 T3.2 T3.5 T4.2 T4.5 U2.2 U2.7 U3.2

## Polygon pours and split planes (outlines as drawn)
18V_1 on Top Layer "TOP_LAYER_18V_1_P276" (solid, remove dead copper, pour order 276): 1139.24,1235.51 1207.88,1235.51 1265.54,1177.84 1334.88,1177.84 1342.88,1185.84 1342.88,1258.84 1304.88,1296.84 1162.9,1296.84 1149.24,1310.51 1054.24,1310.51 1029.24,1285.51 1029.24,1170.51 1022.62,1163.9 1015.85,1163.9 1009.24,1170.51 1009.24,1200.51 909.24,1300.51 855.69,1300.51 849.24,1294.05 849.24,1251.81 850.54,1250.51 889.24,1250.51 904.24,1235.51 904.24,1105.51 909.24,1100.51 1046.64,1100.51 1064.24,1118.11 1064.24,1231.04 1068.71,1235.51
SGND_1 on Top Layer "TOP_LAYER_SGND_1_P274" (solid, remove dead copper, pour order 274): 1164.24,1210.51 1220.83,1153.9 1335.83,1153.9 1349.88,1139.84 1349.88,1093.01 1332.37,1075.51 1284.21,1075.51 1269.21,1090.51 1104.24,1090.51 1079.24,1115.51 1079.24,1215.51 1084.24,1220.51 1154.24,1220.51
-5V_1 on Top Layer "TOP_LAYER_-5V_1_P272" (solid, remove dead copper, pour order 272): 1272.88,1053.84 1261.21,1065.51 912.04,1065.51 899.22,1078.33 899.22,1225.51 896.72,1228.01 889.24,1228.01 850.54,1228.01 849.24,1226.71 849.24,1186.81 859.24,1176.81 859.24,1063.01 916.74,1005.51 917.94,1005.51 942.94,980.51 1051.74,980.51 1075.34,1004.11 1230.61,1004.11 1259.88,974.84 1327.85,974.84 1350.88,997.88 1350.88,1041.84 1338.88,1053.84
-5V_2 on Top Layer "TOP_LAYER_-5V_2_P270" (solid, remove dead copper, pour order 270): 1124.24,675.51 1125.67,676.95 1337.7,676.95 1349.88,689.13 1349.88,742.61 1339.64,752.84 1145.32,752.84 1137.99,745.51 1039.24,745.51 974.24,745.51 906.74,745.51 884.24,768.01 884.24,858.31 890.11,864.18 890.11,902.14 884.24,908.01 848.04,908.01 846.74,906.71 846.74,866.81 856.74,856.81 856.74,743.01 914.24,685.51 915.44,685.51 925.44,675.51 1064.24,675.51
18V_2 on Top Layer "TOP_LAYER_18V_2_P268" (solid, remove dead copper, pour order 268): 1237.88,950.84 1218.21,970.51 1144.24,970.51 1078.71,970.51 1024.24,916.04 1024.24,855.51 1014.24,855.51 1009.24,860.51 1009.24,925.51 989.24,945.51 934.24,945.51 904.24,975.51 850.69,975.51 844.24,969.05 844.24,926.81 845.54,925.51 896.2,925.51 916.2,905.51 916.2,854.97 899.24,838.01 899.24,780.51 904.24,775.51 1041.64,775.51 1059.24,793.11 1059.24,890.51 1079.24,910.51 1134.24,910.51 1242.21,910.51 1247.88,904.84 1275.88,876.84 1327.56,876.84 1348.88,898.16 1348.88,940.28 1338.31,950.84
18V_3 on Top Layer "TOP_LAYER_18V_3_P266" (solid, remove dead copper, pour order 266): 1142.92,653.66 1340.73,653.66 1349.88,644.51 1349.88,591.08 1335.64,576.84 1273.88,576.84 1245.51,605.21 1170.21,605.21 1158.66,593.66 1132.92,593.66 1073.41,593.66 1057.92,578.17 1057.92,476.26 1040.33,458.66 902.92,458.66 902.92,526.16 914.89,538.12 914.89,588.66 898.33,605.21 847.67,605.21 844.52,608.36 844.52,646.29 848.45,650.22 911.36,650.22 932.92,628.66 987.92,628.66 1007.92,608.66 1007.92,543.66 1012.92,538.66 1022.92,538.66 1022.92,599.19 1077.39,653.66
-5V_3 on Top Layer "TOP_LAYER_-5V_3_P264" (solid, remove dead copper, pour order 264): 1101.41,433.02 1250.88,432.84 1271.88,453.84 1332.13,453.84 1346.88,439.09 1346.88,394.84 1324.88,372.84 1135.32,372.84 1123.93,361.46 928.29,361.46 856.72,433.02 856.72,533.03 847.46,542.29 847.46,584.28 849.91,586.72 887.48,586.72 890.09,584.11 890.09,565.13 889.24,564.27 889.24,441.76 897.97,433.02 1052.66,433.02
SGND_2 on Top Layer "TOP_LAYER_SGND_2_P262" (solid, remove dead copper, pour order 262): 1155.37,777.14 1331.01,776.98 1349.88,795.84 1349.88,842.84 1339.4,853.32 1258.4,853.32 1214.52,897.2 1084.24,897.2 1079.24,892.2 1079.24,792.2 1104.24,767.2 1145.44,767.2
SGND_3 on Top Layer "TOP_LAYER_SGND_3_P260" (solid, remove dead copper, pour order 260): 1154.24,582.2 1199.52,582.2 1226.88,554.84 1335.13,554.84 1349.88,540.09 1349.88,495.35 1331.37,476.84 1170.08,476.84 1145.44,452.2 1104.24,452.2 1079.24,477.2 1079.24,577.2 1084.24,582.2
SGND_4 on Top Layer "TOP_LAYER_SGND_4_P258" (solid, remove dead copper, pour order 258): 1153.05,254.89 1153.1,254.84 1335.54,254.84 1349.88,240.51 1349.88,193.16 1332.56,175.84 1195.2,175.84 1144.25,124.89 1103.05,124.89 1078.05,149.89 1078.05,249.89 1083.05,254.89
-5V_4 on Top Layer "TOP_LAYER_-5V_4_P256" (solid, remove dead copper, pour order 256): 1112.99,108.92 1202.96,108.92 1250.88,156.84 1348.88,156.84 1359.88,145.84 1359.88,87.51 1307.88,35.51 1121.74,35.51 902.47,35.51 856.72,81.26 856.72,210.51 847.46,219.79 847.46,260.51 852.46,265.51 887.99,265.51 890.48,263.02 892.98,260.52 895.49,258.01 895.49,214.56 885.69,204.77 885.69,118.1 894.88,108.92
18V_4 on Top Layer "TOP_LAYER_18V_4_P254" (solid, remove dead copper, pour order 254): 1144.78,328.66 1249.69,328.66 1278.88,357.84 1333.63,357.84 1349.88,341.59 1349.88,290.02 1328.51,268.66 1142.92,268.66 1127.92,268.66 1068.4,268.66 1052.92,253.17 1052.92,151.26 1035.32,133.66 901.38,133.66 897.92,137.12 897.92,201.16 909.88,213.12 909.88,269.58 899.24,280.21 850.54,280.21 848.04,282.71 848.04,319.02 854.24,325.22 906.36,325.22 927.92,303.66 982.92,303.66 1002.92,283.66 1002.92,218.66 1007.92,213.66 1017.92,213.66 1017.92,274.19 1072.39,328.66
no net on Top Layer "TOP_LAYER_NONET_P228" (solid, remove dead copper, pour order 228): 1144.24,970.51
no net on Top Layer "TOP_LAYER_NONET_P226" (solid, remove dead copper, pour order 226): 1144.78,328.66
NetC27_1 on Top Layer "TOP_LAYER_NETC27_1_P224" (solid, remove dead copper, pour order 224): 272,914 349,914 358,905 358,855 342,839 273.75,839 266,846.75 266,908
NetC31_1 on Top Layer "TOP_LAYER_NETC31_1_P222" (solid, remove dead copper, pour order 222): 287.38,1016.19 283.58,1020 197,1020 176.24,1040.76 176.24,1127.34 168.76,1134.82 109.34,1134.82 98,1123 98,993 109,982 229,982 236.5,974.5 283,928 330,928 332,930 332,971.58
GND on Top Layer "TOP_LAYER_GND_P220" (solid, remove dead copper, pour order 220): 83,943.28 27,887.28 27,839 27,328 60,295 115.51,295 206,204.51 206,94 214,86 295,86 394,185 394,745 385,754 297,754 206,845 206,901.5 164.22,943.28
HB on Top Layer "TOP_LAYER_HB_P204" (solid, remove dead copper, pour order 204): 163,552 174.27,563.27 284.73,563.27 296,552 296,426 279.74,409.74 179.26,409.74 163,426
HB on Top Layer "TOP_LAYER_HB_P202" (solid, remove dead copper, pour order 202): 399.88,352.84 399.88,282.84 407.53,275.2 467.23,275.2 474.88,282.84 474.88,352.84 464.88,362.84 409.88,362.84
HB on Top Layer "TOP_LAYER_HB_P200" (solid, remove dead copper, pour order 200): 399.88,647.84 399.88,577.84 407.53,570.2 467.24,570.2 474.88,577.84 474.88,647.84 464.88,657.84 409.88,657.84
HB on Top Layer "TOP_LAYER_HB_P198" (solid, remove dead copper, pour order 198): 399.9,920.9 399.9,850.9 407.55,843.25 467.25,843.25 474.9,850.9 474.9,920.9 464.9,930.9 409.9,930.9
20V on Top Layer "TOP_LAYER_20V_P196" (solid, remove dead copper, pour order 196): 311,553 311,581 320,590 375,590 391,574 391,482.82 377,468.82 377,427 358,408 358,306 394,270 394,189 388,183 314,183 311,186
no net on Top Layer "TOP_LAYER_NONET_P172" (solid, remove dead copper, pour order 172): 51.13,660.62
HB on Top Layer "TOP_LAYER_HB_P158" (solid, remove dead copper, pour order 158): 399.9,1237.84 399.9,1167.84 407.55,1160.2 467.26,1160.2 474.9,1167.84 474.9,1237.84 464.9,1247.84 409.9,1247.84
NetD9_2 on Top Layer "TOP_LAYER_NETD9_2_P132" (solid, remove dead copper, pour order 132): 826.76,180.51 817.37,189.91 770.81,189.91 761.41,180.51 696.41,180.51 689.21,173.31 689.21,131.46 739.22,81.46 780.16,40.51 834.24,40.51 839.24,45.51 839.24,102.68 826.76,115.16
NetC44_2 on Top Layer "TOP_LAYER_NETC44_2_P130" (solid, remove dead copper, pour order 130): 784.71,224.32 790.37,218.66 825.63,218.66 829.24,222.26 829.21,318.13 822.75,324.59 713.19,324.59 694.21,324.59 684.21,314.59 684.21,281.79 691.41,274.59 754.21,274.59 784.71,244.09
NetC42_2 on Top Layer "TOP_LAYER_NETC42_2_P118" (solid, remove dead copper, pour order 118): 736.19,648.5 821.22,648.5 829.22,640.51 829.22,549.92 824.81,545.51 806.72,545.51 784.22,545.51 754.22,575.51 691.42,575.51 684.22,582.71 684.22,615.51 694.22,625.51 713.19,625.51
NetD7_2 on Top Layer "TOP_LAYER_NETD7_2_P116" (solid, remove dead copper, pour order 116): 739.22,381.46 759.22,361.46 830.18,361.46 836.72,368 836.72,430.52 826.77,440.48 826.77,502.98 814.24,515.51 774.85,515.51 770.81,511.47 770.81,489.91 761.42,480.51 696.42,480.51 689.22,473.31 689.22,431.46
NetD4_2 on Top Layer "TOP_LAYER_NETD4_2_P110" (solid, remove dead copper, pour order 110): 689.23,751.44 698.79,761 753.92,761 769.24,776.32 769.24,830.51 772.39,833.66 815.07,833.66 829.23,819.5 829.23,784.57 836.74,777.06 836.74,687.07 830.18,680.51 739.24,680.51 699.91,680.51 688.98,691.44 688.98,730.26 689.23,730.52
NetC37_2 on Top Layer "TOP_LAYER_NETC37_2_P108" (solid, remove dead copper, pour order 108): 778.43,864.57 763.86,850 688.04,850 684.23,853.81 684.23,914.57 694.23,924.57 713.21,924.57 759.19,970.55 824.39,970.51 829.23,965.67 829.23,869.41 824.39,864.57
no net on Top Layer "TOP_LAYER_NONET_P104" (solid, remove dead copper, pour order 104): 694.24,965.51
NetC43_2 on Top Layer "TOP_LAYER_NETC43_2_P098" (solid, remove dead copper, pour order 98): 691.44,1165.51 684.24,1172.71 684.24,1205.51 694.24,1215.51 713.21,1215.51 791.76,1294.05 824.24,1294.05 829.24,1289.05 829.24,1186.81 827.94,1185.51 774.24,1185.51 754.24,1165.51
NetD8_2 on Top Layer "TOP_LAYER_NETD8_2_P096" (solid, remove dead copper, pour order 96): 809.24,1163.9 829.24,1143.9 829.24,1075.51 844.24,1060.51 844.24,1010.51 829.24,995.51 706.44,995.51 689.24,1012.71 689.24,1063.31 696.43,1070.51 761.43,1070.51 774.24,1083.31 774.24,1155.51 782.62,1163.9
VIN+ on Bottom Layer "BOTTOM_LAYER_VIN+_P278" (solid, remove dead copper, pour order 278): 287.4,1268.43 312.99,1242.84 361.23,1242.84 376,1228.07 376,1182.2 370.61,1176.81 165.45,1176.81 163,1179.26 163,1222.1 196.85,1255.95 196.85,1388.17 206.32,1397.64 279.75,1397.64 287.4,1389.99
GND on Bottom Layer "BOTTOM_LAYER_GND_P218" (solid, remove dead copper, pour order 218): 73,1229.5 62.99,1239.79 62.99,1381.12 79.51,1397.64 141.73,1397.64 149.61,1389.76 149.61,1299.61 148,1298 148,1118 142,1112 129,1112 115,1098 115,1060.35 162,1013.35 162,917 194,885 194,822 195,821 184,810 155,810 143,798 143,743 155,731 312,731 343,762 418,762 427,753 427,684 394,651 394,607.5 402,599.5 402,356 497,261 497,77 438,18 61.08,18 20,59.08 20,528 20,775 53,808 53,892 87,926 87,998 49,1036 49,1094 88,1133 88,1214.5 81,1221.5
NetC24_1 on Bottom Layer "BOTTOM_LAYER_NETC24_1_P216" (solid, remove dead copper, pour order 216): 319.5,1051.5 274.5,1051.5 261,1065 261,1089 268,1096 367.49,1096 377,1105.51 377,1147 374,1150 225.5,1150 215.8,1159.7 167.19,1159.7 163,1155.51 163,1121.22 174,1110.22 179,1105.22 179,1011 180,1010 180,974 183,971 224.5,971 238.5,985 321,985 326,990 326,1045
NetC27_1 on Bottom Layer "BOTTOM_LAYER_NETC27_1_P214" (solid, remove dead copper, pour order 214): 327,936 327,956 316,967 240,967 230,957 184,957 178,951 178,914 190.18,902 202,890.18 202,748.5 212.5,738 300,738 333,771 413,771 431,789 431,853 424,860 364.5,860 358,866.5 358,905
20V on Bottom Layer "BOTTOM_LAYER_20V_P210" (solid, remove dead copper, pour order 210): 205,586 205,513 220,498 379,498 394,513 394,582 386,590 209,590
HB on Bottom Layer "BOTTOM_LAYER_HB_P208" (solid, remove dead copper, pour order 208): 399,1228 411,1240 467,1240 488,1219 488,342 458,312 421,312 330,403 221,403 214,410 214,478 223.64,487.64 385.64,487.64 407,509 407,649 445,687 445,867 399,913
20V on Bottom Layer "BOTTOM_LAYER_20V_P206" (solid, remove dead copper, pour order 206): 380,272 318,272 298,252 298,218 311,205 311,128.6 315,124.6 362.6,124.6 397,159 397,255
no net on Bottom Layer "BOTTOM_LAYER_NONET_P164" (solid, remove dead copper, pour order 164): 128.21,352.84
no net on Bottom Layer "BOTTOM_LAYER_NONET_P146" (solid, remove dead copper, pour order 146): -189.01,31.69

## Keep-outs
Keep-Out Layer:
  text ".Layer_Name" at 577,-858.49 h60

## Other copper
Top Layer:
  text ".Layer_Name" at 577,-858.49 h60
Bottom Layer:
  pour cut-out: 156.95,521.28 156,520.33 156,490 171.29,490 193.68,512.39 193.68,520.32 189.59,524.41 159,524.41
  pour cut-out: 195.36,455.91 207,455.91 209.26,453.65 209.26,405.26 208,404 193.38,404 192,405.38 192,452.55
  text ".Layer_Name" at 577,-858.49 h60

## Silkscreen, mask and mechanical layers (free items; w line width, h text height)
Top Overlay:
  text "PMP40970" at 992.92,1350 h72.83
  text "GND" at 5,1275 h40
  text "VIN+" at 265,1275 h40
  text ".Layer_Name" at 577,-858.49 h60
Bottom Overlay:
  text ".Layer_Name" at 577,-858.49 h60
Top Paste:
  text ".Layer_Name" at 577,-858.49 h60
Bottom Paste:
  text ".Layer_Name" at 577,-858.49 h60
Top Solder:
  text ".Layer_Name" at 577,-858.49 h60
  text ".Layer_Name" at 577,-858.49 h60
Bottom Solder:
  text ".Layer_Name" at 577,-858.49 h60
Drill Guide:
  text ".Layer_Name" at 577,-858.49 h60
M1 Board Outline:
  the board outline again, w10
  text ".Layer_Name" at 577,-858.49 h60
M2 Board Dimensions:
  rectangle: 0,-275 125,-150
  rectangle: 125,-400 500,-275
  lines w7: 0,-275 1000,-275 ; 125,-400 125,-150 ; 250,-400 250,-150 ; 500,-400 500,-150 ; 750,-400 750,-150 ; 0,-400 1000,-400 1000,-150 0,-150 0,-400
  text ".Layer_Name" at 577,-858.49 h60
M3 3D STEP Top:
  text ".Layer_Name" at 577,-858.49 h60
M4 3D STEP Bottom:
  text ".Layer_Name" at 577,-858.49 h60
M5 Assembly Top:
  lines w10: -292,-930.17 6308,-930.17 ; -292,-726.83 6310,-726.83 ; -292,-523.5 -292,-1133.5 3713,-1133.5 6310,-1133.5 6310,-523.5 -291.5,-523.5 -291.5,-1133.5 1284,-1133.5 ; 2173,-1133.5 2173,-523.5 ; 3440,-726.83 3440,-523.5 ; 4280,-726.83 4280,-523.5 ; 4902,-1140 4902,-937.17
  text "COMPONENTS MARKED 'DNP' SHOULD NOT BE POPULATED." at 1153.5,-318.5 h60
  text "ASSEMBLY VARIANT:" at 1153,-434 h60
  text ".VariantName" at 2189,-434 h60
  text "PCB VIEWED FROM TOP SIDE" at -228.5,-655.67 h60
  text "BOARD #:" at 2248,-655.67 h60
  text ".PRJ_Number" at 2793.5,-655.67 h60
  text "REV:" at 3638,-655.67 h60
  text ".PCB_Rev" at 3929.5,-655.67 h60
  text "SVN REV:" at 4476,-655.67 h60
  text ".VersionControl_RevNumber" at 4982,-655.67 h60
  text "TID #:" at 2248,-859 h60
  text ".TID" at 2793.5,-859 h60
  text "PLOT NAME =" at -228.5,-1064.34 h60
  text ".plot_File_Name" at 577,-1064.34 h60
  text "GENERATED    :" at 2250,-1064.34 h60
  text ".Print_Date" at 3119.5,-1064.34 h60
  text ".Print_Time" at 3848.5,-1064.34 h60
  text "TEXAS INSTRUMENTS" at 5113,-1064.34 h60
M6 Assembly Bottom:
  lines w10: -292.5,-727.33 6309.5,-727.33 ; -290.5,-930.67 6309.5,-930.67 ; 1115.5,-1140.5 1115.5,-937.67 ; 1737.5,-727.33 1737.5,-524 ; 2577.5,-727.33 2577.5,-524 ; 3844.5,-1134 3844.5,-524 ; 4733.5,-1134 6309,-1134 6309,-524 -292.5,-524 -292.5,-1134 2304.5,-1134 6309.5,-1134 6309.5,-524
  text "COMPONENTS MARKED 'DNP' SHOULD NOT BE POPULATED." at 6102,-318 h60
  text ".VariantName" at 5058,-434 h60
  text "ASSEMBLY VARIANT:" at 6097,-434 h60
  text ".VersionControl_RevNumber" at 1035.5,-656.17 h60
  text "SVN REV:" at 1541.5,-656.17 h60
  text ".PCB_Rev" at 2088,-656.17 h60
  text "REV:" at 2379.5,-656.17 h60
  text ".PRJ_Number" at 3224,-656.17 h60
  text "BOARD #:" at 3769.5,-656.17 h60
  text "PCB VIEWED FROM BOTTOM SIDE" at 6246,-656.17 h60
  text ".TID" at 3224,-859.5 h60
  text "TID #:" at 3769.5,-859.5 h60
  text "TEXAS INSTRUMENTS" at 904.5,-1064.84 h60
  text ".Print_Time" at 2169,-1064.84 h60
  text ".Print_Date" at 2898,-1064.84 h60
  text "GENERATED    :" at 3767.5,-1064.84 h60
  text ".plot_File_Name" at 5440.5,-1064.84 h60
  text "PLOT NAME =" at 6246,-1064.84 h60
M9 Title Sheet:
  drawing of 57 lines, arcs and shapes, not listed
  text "1" at 739.84,8036.5 h70
  text "2" at 3235.5,8036.5 h70
  text "3" at 5724.84,8036.5 h70
  text "4" at 8231.51,8036.5 h70
  text "5" at 10730.5,8036.5 h70
  text "6" at 13235.5,8036.5 h70
  text "A" at -416.5,6893.5 h70
  text "A" at 14383.5,6893.5 h70
  text "B" at -416.5,4513.5 h70
  text "B" at 14383.5,4513.5 h70
  text "C" at -416.5,2138.5 h70
  text "C" at 14383.5,2138.5 h70
  text "PROJECT TITLE:" at 11343.5,277.5 h45
  text ".PRJ_Title" at 11393.5,144.17 h70
  text "DESIGNED FOR:" at 11343.5,-23.5 h45
  text ".PRJ_Customer" at 11393.5,-163.5 h70
  text "D" at -416.5,-231.5 h70
  text "D" at 14383.5,-231.5 h70
  text "FILE NAME:" at 11343.5,-323.5 h45
  text ".PCB_File_Name_No_Path" at 11393.5,-443.5 h70
  text "Texas Instruments (TI) and/or its licensors do not warrant the accuracy or completeness of this specification" at 6374,-605.34 h45
  text "ENGINEER:" at 11343.5,-613.5 h45
  text "LAYOUT BY:" at 12848.5,-613.5 h45
  text "or any information contained therein. TI and/or its licensors do not warrant that this design will meet" at 6329.01,-718 h45
  text ".PRJ_Engineer" at 11393.5,-768.49 h70
  text ".PCB_Layout" at 12899,-768.49 h70
  text "the specifications, will be suitable for your application or fit for any particular purpose, or will operate in" at 6329.01,-830.67 h45
  text ".Layer_Name" at 577,-858.49 h60
  text "ALTIUM DESIGNER VERSION:" at 12848.5,-923.5 h45
  text "an implementation. TI and/or its licensors do not warrant that the design is production worthy. You should" at 6329.01,-943.33 h45
  text "completely validate and test your design implementation to confirm the system functionality for your application." at 6374,-1056 h45
  text ".print_Scale" at 11393.5,-1056.83 h70
  text ".Application_BuildNumber" at 12899,-1056.83 h70
  text "1" at 739.84,-1263.5 h70
  text "2" at 3235.5,-1263.5 h70
  text "3" at 5724.84,-1263.5 h70
  text "4" at 8231.51,-1263.5 h70
  text "5" at 10730.5,-1263.5 h70
  text "6" at 13235.5,-1263.5 h70
M10 Fab Notes:
  drawing of 189 lines, arcs and shapes, not listed
  text "DESIGN INFORMATION" at 12382.02,6356.17 h60
  text "MIN. TRACK WIDTH:" at 11737.46,6224.05 h60
  text "10" at 12833.7,6224.05 h60
  text "MIL" at 12988.46,6224.05 h60
  text "7.874" at 12667.32,6102.36 h60
  text "MIN. CLEARANCE:" at 11737.46,6099.92 h60
  text "MIL" at 12988.46,6099.92 h60
  text "MIN. VIA PAD SIZE:" at 11737.46,5975.8 h60
  text "24" at 12803.71,5975.8 h60
  text "MIL" at 12988.46,5975.8 h60
  text "0.05mm (2MIL)" at 12432.46,5845.9 h60
  text "MINIMUM ANNULAR RING" at 11408.23,5837.67 h60
  text "EXTERNAL" at 13140.46,5837.67 h60
  text "PER" at 11608.23,5727.55 h60
  text "IPC-D-275 CLASS 2 LEVEL C" at 11828.23,5727.54 h60
  text "MIL, HOLES" at 13316.46,5627.07 h60
  text "+/-" at 12924,5618.48 h60
  text "+/-" at 13778,5618.48 h60
  text "REGISTRATION TOLERANCES:" at 11408.23,5617.42 h60
  text "METAL" at 12608,5617.42 h60
  text "5" at 13184.2,5617.42 h60
  text "3" at 14017.2,5617.42 h60
  text "MIL" at 14133.46,5617.42 h60
  text "HOLE SIZE TOLERANCE (UNLESS OTHERWISE SPECIFIED):" at 11408.23,5519.1 h60
  text "+/-" at 13778,5516.23 h60
  text "3" at 14017.2,5515.17 h60
  text "MIL" at 14133.46,5515.17 h60
  text "MATERIAL:" at 11333.46,5377.52 h60
  text "FR-4 High Tg" at 12319.9,5249 h60
  text "X" at 12175.46,5241.01 h60
  text "FR-408" at 11754.46,5236.49 h60
  text "OTHER" at 13242.46,5236.49 h60
  text "62 MIL (1.6mm) +/-10%" at 12074.56,5093.46 h60
  text "X" at 11954.46,5091.01 h60
  text "THICKNESS:" at 11408.23,5085.24 h60
  text "OTHER" at 13359.46,5085.24 h60
  text "TOLERANCE:" at 11408.23,4946.92 h60
  text "X" at 12256.46,4946.92 h60
  text "ANSI IPC-6012 TYPE 3 CLASS 2" at 12434.48,4946.92 h60
  text "OTHER +/-" at 12434.46,4802.73 h60
  text "BOW & TWIST:" at 11408.23,4657.54 h60
  text "X" at 12256.46,4657.54 h60
  text "ANSI IPC-6012 TYPE 3 CLASS 2" at 12434.48,4657.54 h60
  text "OTHER +/-" at 12434.46,4510.85 h60
  text "DRILLING:" at 11333.46,4380.23 h60
  text "NC_DRILL FILES" at 13094.46,4275.04 h60
  text "REFERENCE:" at 11408.23,4271.1 h60
  text "X" at 12065.46,4271.01 h60
  text "AS SHOWN" at 12243.46,4271.1 h60
  text "X" at 12966.46,4271.1 h60
  text "OTHER" at 13392.46,4128.85 h60
  text "PTH COPPER THICKNESS:" at 11407.91,4125.32 h60
  text "X" at 12547.14,4125.32 h60
  text "20-30 um" at 12675.14,4125.32 h60
  text "BOARD FINISH:" at 11333.46,3977.73 h60
  text "SILKSCREEN:" at 11488.68,3867.6 h60
  text "X" at 12446.46,3867.6 h60
  text "TOP" at 12563.46,3867.6 h60
  text "X" at 12956.46,3867.6 h60
  text "BOTTOM" at 13074.46,3867.6 h60
  text "SILKSCREEN COLOR:" at 11488.68,3712.41 h60
  text "X" at 12445.46,3712.41 h60
  text "WHITE" at 12563.46,3712.41 h60
  text "OTHER" at 13074.46,3712.41 h60
  text "X" at 12576.46,3568.96 h60
  text "GREEN" at 12694.46,3568.96 h60
  text "OTHER" at 13312.46,3568.96 h60
  text "SOLDER RESIST COLOR:" at 11488.68,3562.1 h60
  text "X" at 12576.46,3414.71 h60
  text "MATTE" at 12694.46,3414.71 h60
  text "SEMI-GLOSS" at 13312,3414.07 h60
  text "IMMERSION GOLD (ENIG)" at 12394.46,3241.94 h60
  text "ENEPIG" at 13732,3234.72 h60
  text "SURFACE FINISH:" at 11333.46,3233.72 h60
  text "X" at 12216.46,3233.72 h60
  text "IMM. TIN/SILVER OR EQUIV" at 11663,3096.4 h60
  text "OTHER" at 13094.46,3092.47 h60
  text "ARRAY/PANEL:" at 11333.46,2937.09 h60
  text "CUT AND TRIM PER M1 BOARD OUTLINE" at 12394.46,2928.87 h60
  text "N.C. ROUTE" at 12394.46,2792.9 h60
  text "X" at 13082.46,2792.9 h60
  text "V. SCORE" at 13260.46,2792.9 h60
  text "CERTIFICATION:" at 11333.46,2663.77 h60
  text "MATERIALS AND WORKMANSHIP FOR ALL PCBS" at 12058.46,2663.77 h60
  text "TO MEET OR EXCEED THE REQUIREMENTS OF:" at 12058.46,2569.71 h60
  text "X" at 11695.97,2441.08 h60
  text "ANSI IPC-A-600F CLASS ->" at 11823.96,2441.08 h60
  text "X" at 13471.97,2441.08 h60
  text "2" at 13581.96,2441.08 h60
  text "1" at 13266.96,2439.58 h60
  text "3" at 13935.96,2439.58 h60
  text "X" at 12507.97,2293.39 h60
  text "RoHS" at 12635.96,2293.39 h60
  text "OTHER" at 13280.36,2293.39 h60
  text "PER ORDER" at 13677.42,2293.39 h60
  text "ALL BOARDS MUST MEET OR EXCEED UL94-V0 REQUIREMENTS." at 11361,2139.57 h60
  text "PCB MUST BEAR THE UL94V-0 UL REGISTERED MATERIAL ID NUMBER" at 11361,2023.5 h60
  text "ADDITIONAL REQUIREMENTS:" at 11333.46,1854.08 h60
  text "MICROSECTION:" at 11408.23,1746.95 h60
  text "YES" at 12313.96,1746.95 h60
  text "REQUIRED" at 13175.46,1602.62 h60
  text "BARE BOARD ELEC. TEST:" at 11408.23,1599.76 h60
  text "NONE" at 12713.96,1599.76 h60
  text "X" at 13057.46,1599.76 h60
  text "PER ORDER" at 13767.46,1599.76 h60
  text "XX MIL VIAS REQUIRE NON-CONDUCTIVE FILL AND PLANARIZE" at 11576.38,1394.82 h59
  text "XX MIL VIAS REQUIRE CONDUCTIVE FILL AND PLANARIZE" at 11584.38,1290.84 h60
  text "OUTER XX MIL TRACES REQUIRE 50 OHM SINGLE-ENDED IMPEDANCE" at 11583.39,1127.46 h58
  text "LAYER 2 & 3 (INNER LAYERS) XX MIL WIDE, XX MIL SPACE / TRACES REQUIRE 100 OHM DIFFERENTIAL IMPEDANCE" at 11575.39,891.74 h60
  text ".Layer_Name" at 577,-858.49 h60
M11 Gerber Information:
  lines w10: -292,-930.17 6308,-930.17 ; -292,-726.83 6310,-726.83 ; -292,-523.5 -292,-1133.5 3713,-1133.5 6310,-1133.5 6310,-523.5 -291.5,-523.5 -291.5,-1133.5 1284,-1133.5 ; 2173,-1133.5 2173,-523.5 ; 3440,-726.83 3440,-523.5 ; 4280,-726.83 4280,-523.5 ; 4902,-1140 4902,-937.17
  text "ALL ARTWORK VIEWED FROM TOP SIDE" at -228.5,-655.67 h60
  text "BOARD #:" at 2248,-655.67 h60
  text ".PRJ_Number" at 2793.5,-655.67 h60
  text "REV:" at 3638,-655.67 h60
  text ".PCB_Rev" at 3929.5,-655.67 h60
  text "SVN REV:" at 4476,-655.67 h60
  text ".VersionControl_RevNumber" at 4982,-655.67 h60
  text "LAYER NAME =" at -228.5,-858.49 h60
  text "TID #:" at 2248,-859 h60
  text ".TID" at 2793.5,-859 h60
  text "PLOT NAME =" at -228.5,-1064.34 h60
  text ".plot_File_Name" at 577,-1064.34 h60
  text "GENERATED    :" at 2250,-1064.34 h60
  text ".Print_Date" at 3119.5,-1064.34 h60
  text ".Print_Time" at 3848.5,-1064.34 h60
  text "TEXAS INSTRUMENTS" at 5113,-1064.34 h60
